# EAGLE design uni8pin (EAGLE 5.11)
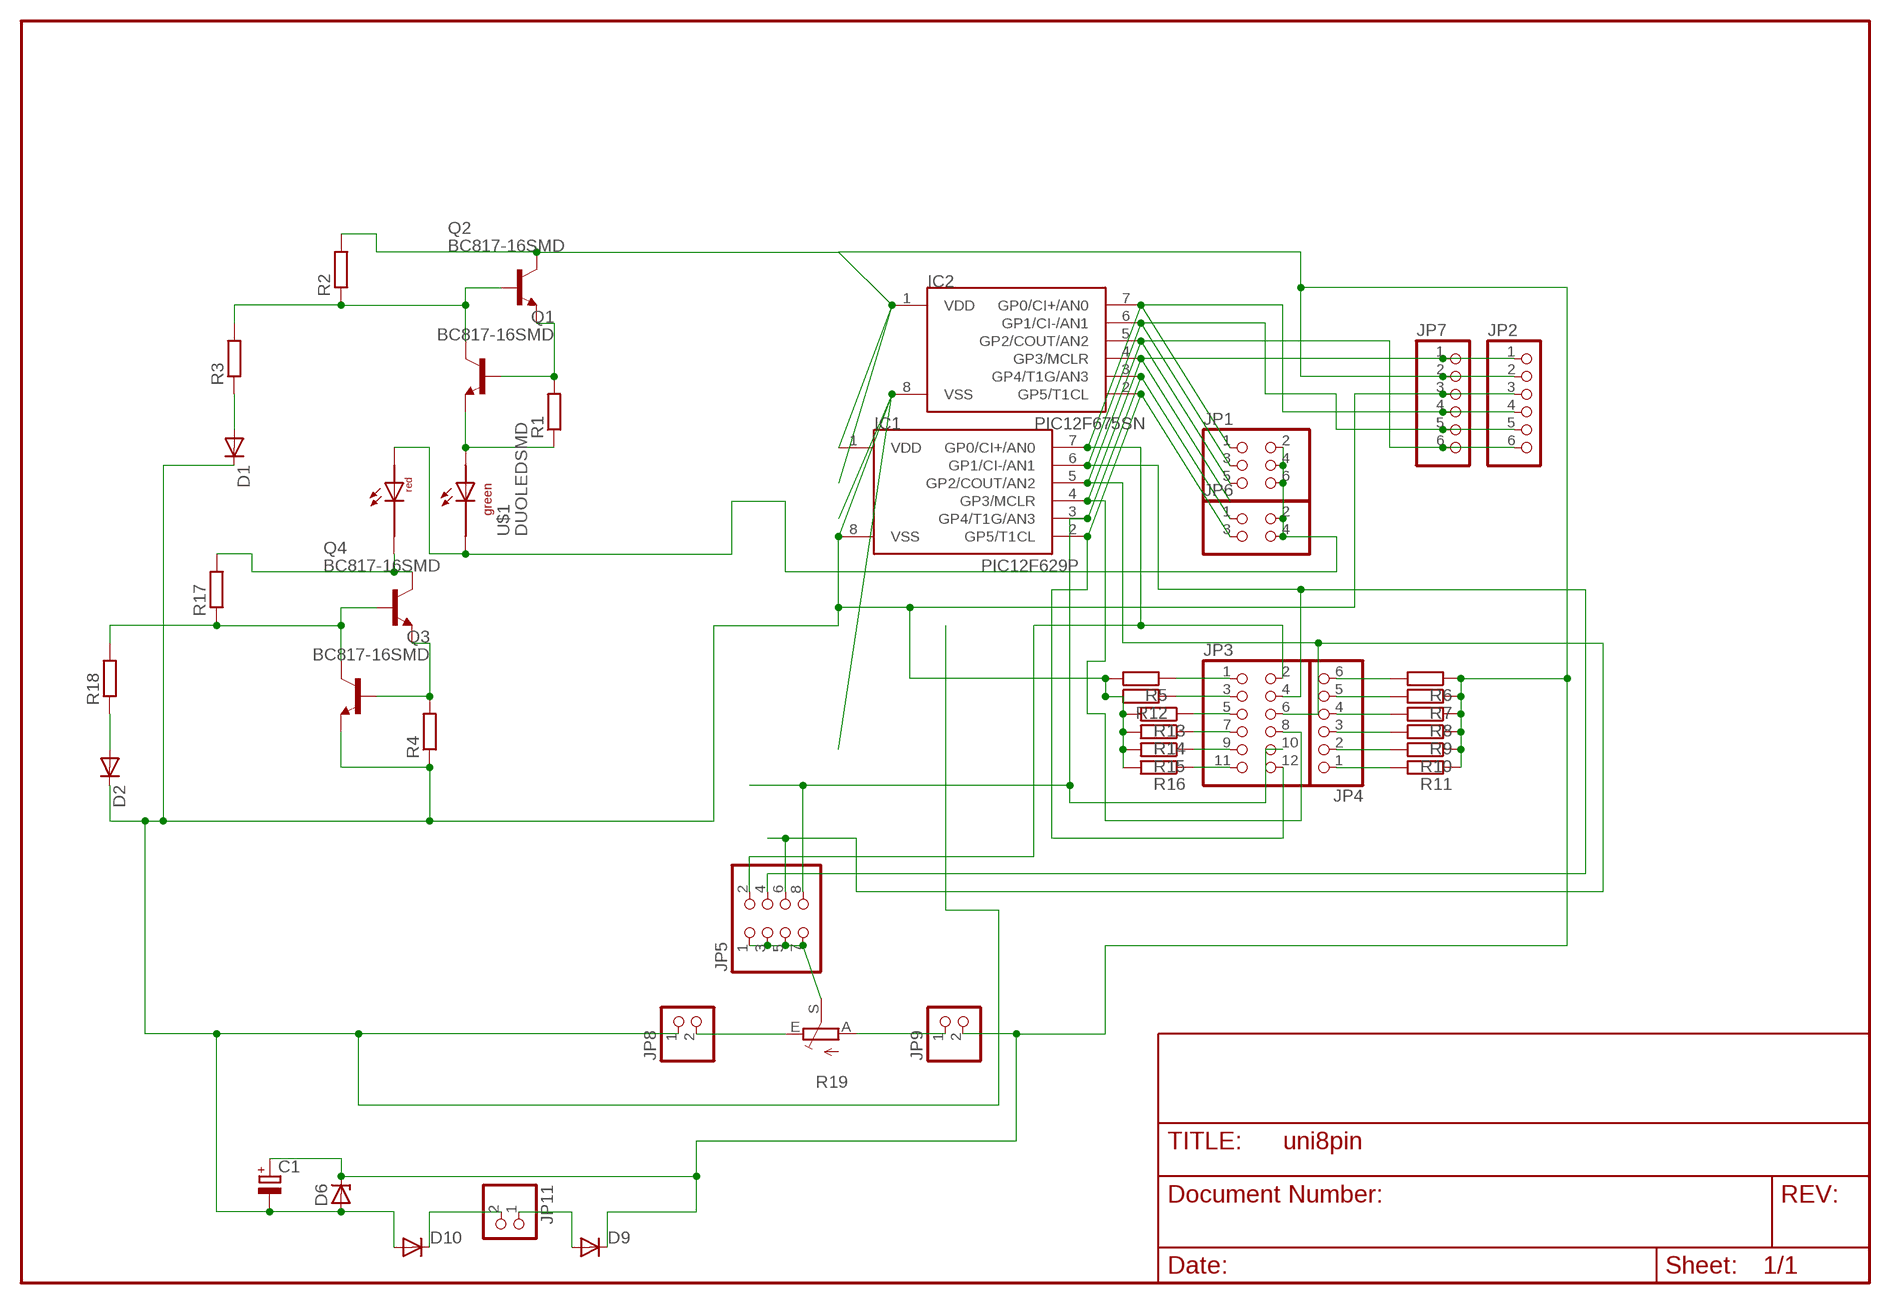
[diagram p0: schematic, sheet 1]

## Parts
C1  CPOL-EU5-13  [2,5-5-FLAT]
D1  DIODE-MINIMELF  [MINIMELF]
D2  DIODE-MINIMELF  [MINIMELF]
D6  ZENER-DIODEZD-2.5  [ZDIO-2.5]
D9  DIODE-D-5  [D-5]
D10  DIODE-D-5  [D-5]
IC1  PIC12F629P  [DIL8]
IC2  PIC12F675SN  [SO-08]
JP1  PINHD-2X3  [2X03]
JP2  PINHD-1X6  [1X06]
JP3  PINHD-2X6  [2X06]
JP4  PINHD-1X6  [1X06]
JP5  PINHD-2X4  [2X04]
JP6  PINHD-2X2  [2X02]
JP7  PINHD-1X6  [1X06]
JP8  PINHD-1X2  [1X02]
JP9  PINHD-1X2  [1X02]
JP11  PINHD-1X2  [1X02]
Q1  BC817-16SMD  [SOT23-BEC]
Q2  BC817-16SMD  [SOT23-BEC]
Q3  BC817-16SMD  [SOT23-BEC]
Q4  BC817-16SMD  [SOT23-BEC]
R1  R-EU_R1206  [R1206]
R2  R-EU_R1206  [R1206]
R3  R-EU_R1206  [R1206]
R4  R-EU_R1206  [R1206]
R5  R-EU_R1206  [R1206]
R6  R-EU_R1206  [R1206]
R7  R-EU_R1206  [R1206]
R8  R-EU_R1206  [R1206]
R9  R-EU_R1206  [R1206]
R10  R-EU_R1206  [R1206]
R11  R-EU_R1206  [R1206]
R12  R-EU_R1206  [R1206]
R13  R-EU_R1206  [R1206]
R14  R-EU_R1206  [R1206]
R15  R-EU_R1206  [R1206]
R16  R-EU_R1206  [R1206]
R17  R-EU_R1206  [R1206]
R18  R-EU_R1206  [R1206]
R19  TRIM_EU-RAND160  [RANDL]
U$1  DUOLEDSMD  [DUOLEDSMD]

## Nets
N$1: IC1.3(GP4/T1G/AN3) IC2.3(GP4/T1G/AN3) JP3.10 JP5.8 JP6.1
N$2: Q2.C R2.2
N$3: Q1.E R1.1 U$1.AGRN
N$4: JP1.2 JP1.4 JP1.6 JP6.2 JP6.4 U$1.ARED U$1.CGRN
N$5: C1.- D1.C D2.C D6.A D10.A IC1.8(VSS) IC2.8(VSS) JP2.3 JP7.3 JP8.1 Q3.E R4.1 R5.2 R12.2 R13.2 R14.2 R15.2 R16.2
N$6: C1.+ D6.C D9.C IC1.1(VDD) IC2.1(VDD) JP2.2 JP7.2 JP9.2 R6.1 R7.1 R8.1 R9.1 R10.1 R11.1
N$7: Q1.B Q2.E R1.2
N$8: Q1.C Q2.B R2.1 R3.2
N$9: IC1.2(GP5/T1CL) IC2.2(GP5/T1CL) JP3.12 JP6.3
N$10: D1.A R3.1
N$11: IC1.4(GP3/MCLR) IC2.4(GP3/MCLR) JP2.1 JP3.8 JP7.1
N$12: IC1.5(GP2/COUT/AN2) IC2.5(GP2/COUT/AN2) JP1.5 JP2.6 JP3.6 JP5.6 JP7.6
N$13: IC1.6(GP1/CI-/AN1) IC2.6(GP1/CI-/AN1) JP1.3 JP2.5 JP3.4 JP5.4 JP7.5
N$14: IC1.7(GP0/CI+/AN0) IC2.7(GP0/CI+/AN0) JP1.1 JP2.4 JP3.2 JP5.2 JP7.4
N$15: JP4.6 R6.2
N$16: JP4.5 R7.2
N$17: JP4.4 R8.2
N$18: JP4.3 R9.2
N$19: JP4.2 R10.2
N$20: JP4.1 R11.2
N$21: JP3.1 R5.1
N$22: JP3.3 R12.1
N$23: JP3.5 R13.1
N$24: JP3.7 R14.1
N$25: JP3.9 R15.1
N$26: JP3.11 R16.1
N$27: Q4.C R17.2 U$1.CRED
N$28: JP5.1 JP5.3 JP5.5 JP5.7 R19.S
N$29: Q3.B Q4.E R4.2
N$30: Q3.C Q4.B R17.1 R18.2
N$31: JP9.1 R19.A
N$32: JP8.2 R19.E
N$34: D10.C JP11.2
N$35: D9.A JP11.1
N$36: D2.A R18.1

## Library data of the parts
C1 = rcl-2:CPOL-EU: POLARIZED CAPACITOR, European symbol
D1 D2 = diode:DIODE-: DIODE
D6 = diode-1:ZENER-DIODE: Z-Diode
D9 D10 = diode-1:DIODE-: DIODE
IC1 IC2 = microchip-5:PIC12F6*: uPC nW 1k Program Flash memory 2x Timer Comparator 10b A/D converter/ 4xIN
JP1 = pinhead(2):PINHD-2X3: PIN HEADER
JP2 JP7 = pinhead:PINHD-1X6: PIN HEADER
JP3 = pinhead(2):PINHD-2X6: PIN HEADER
JP4 = pinhead(2):PINHD-1X6: PIN HEADER
JP5 = pinhead(2):PINHD-2X4: PIN HEADER
JP6 = pinhead(2):PINHD-2X2: PIN HEADER
JP8 JP9 JP11 = pinhead(2):PINHD-1X2: PIN HEADER
Q1-Q4 = transistor-npn:BC817*: NPN Transistor
R1-R4 R17 R18 = rcl:R-EU_: RESISTOR, European symbol
R5-R16 = rcl-2:R-EU_: RESISTOR, European symbol
R19 = pot:TRIM_EU-: POTENTIOMETER
U$1 = led:DUOLEDSMD

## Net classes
0 default: width 0.3 mm, drill 0.6 mm, clearance 0.2 mm
1 power: width 0.4 mm, drill 0.6 mm, clearance 0.2 mm

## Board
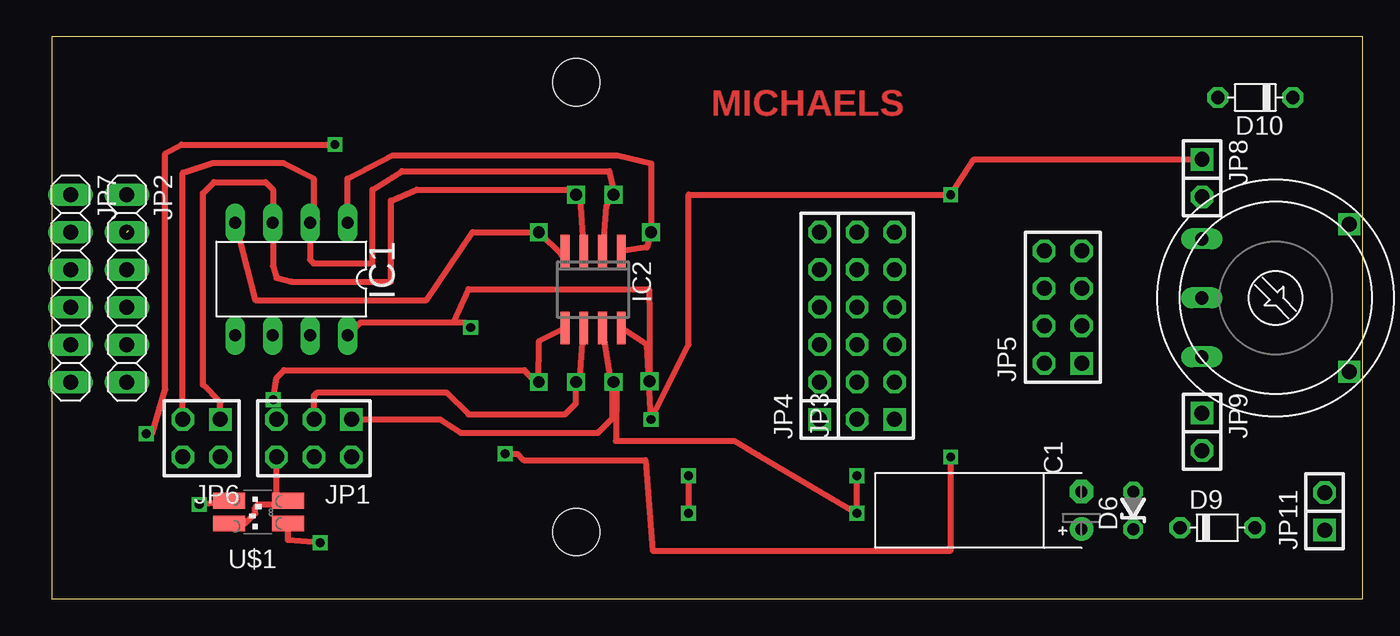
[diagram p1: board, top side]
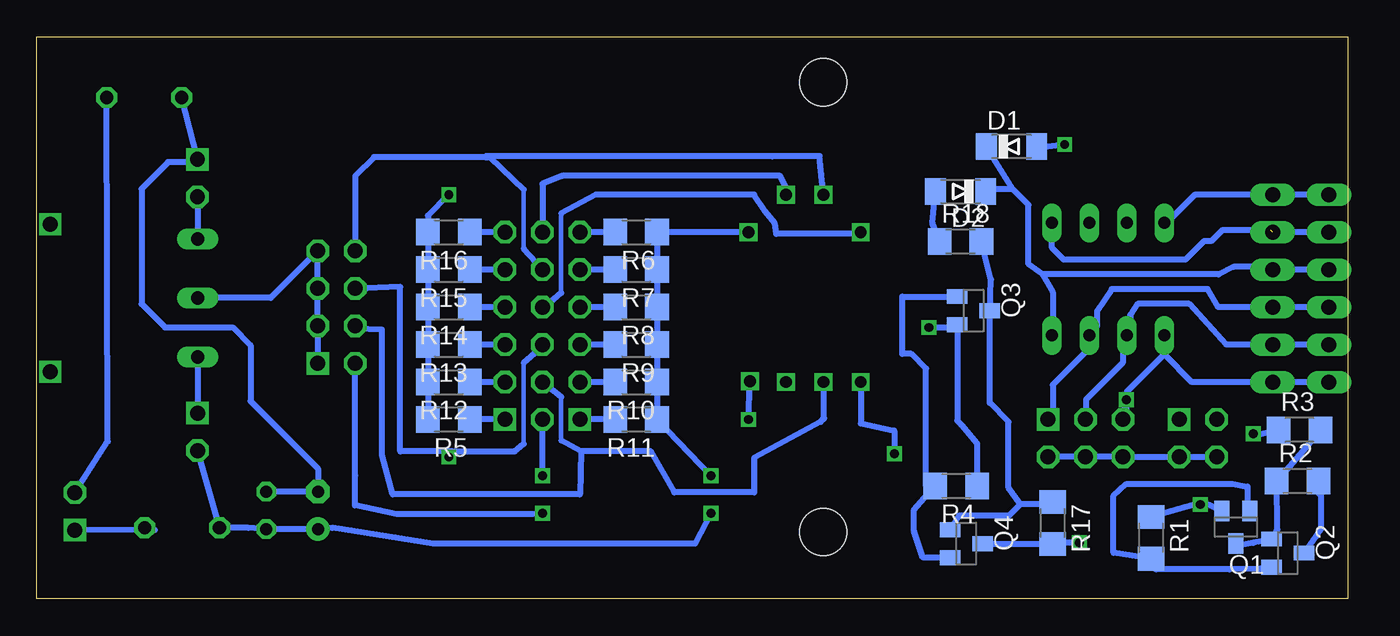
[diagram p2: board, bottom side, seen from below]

Size 88.9 x 38.1 mm. Coordinates in mm from the lower left corner, seen from the top.
Outline: 0,0 88.9,0 88.9,38.1 0,38.1 0,0
Copper layers (1*16): Top 0.035mm / dielectric 1.5mm / Bottom 0.035mm
Design rules "default": minimum track width 10mil, minimum drill 24mil, track to track 8mil, track to pad 8mil, pad to pad 8mil, via to via 8mil, smd to smd 8mil, copper to edge 40mil, drill to drill 8mil, minimum pad ring 10mil, minimum via ring 8mil, stop-mask expansion 4mil, vias tented up to drill 0mil, thermal gap 10mil
Holes 3.2 mm at 35.56,35.02 35.56,4.54

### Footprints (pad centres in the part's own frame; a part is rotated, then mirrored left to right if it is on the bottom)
2,5-5-FLAT = drill 0.813 pad 1.6 round: + -1.27,0 | drill 0.813 pad 1.6 octagon: - 1.27,0
MINIMELF = smd 1.4 x 1.8: A 1.7,0; C -1.7,0
ZDIO-2.5 = drill 0.813 octagon: A 1.27,0; C -1.27,0
D-5 = drill 0.9 octagon: A 2.54,0; C -2.54,0
DIL8 = drill 0.813 long: 1 -3.81,-3.81; 2 -1.27,-3.81; 3 1.27,-3.81; 4 3.81,-3.81; 5 3.81,3.81; 6 1.27,3.81; 7 -1.27,3.81; 8 -3.81,3.81
SO-08 = smd 0.6 x 2.2: 1 -1.905,-2.6; 2 -0.635,-2.6; 3 0.635,-2.6; 4 1.905,-2.6; 5 1.905,2.6; 6 0.635,2.6; 7 -0.635,2.6; 8 -1.905,2.6
2X03 = drill 1.016 square: 1 -2.54,-1.27 | drill 1.016 octagon: 2 -2.54,1.27; 3 0,-1.27; 4 0,1.27; 5 2.54,-1.27; 6 2.54,1.27
1X06 = drill 1.016 long: 1 -6.35,0; 2 -3.81,0; 3 -1.27,0; 4 1.27,0; 5 3.81,0; 6 6.35,0
2X06 = drill 1.016 square: 1 -6.35,-1.27 | drill 1.016 octagon: 2 -6.35,1.27; 3 -3.81,-1.27; 4 -3.81,1.27; 5 -1.27,-1.27; 6 -1.27,1.27; 7 1.27,-1.27; 8 1.27,1.27; 9 3.81,-1.27; 10 3.81,1.27; 11 6.35,-1.27; 12 6.35,1.27
1X06' = drill 1.016 square: 1 -6.35,0 | drill 1.016 octagon: 2 -3.81,0; 3 -1.27,0; 4 1.27,0; 5 3.81,0; 6 6.35,0
2X04 = drill 1.016 square: 1 -3.81,-1.27 | drill 1.016 octagon: 2 -3.81,1.27; 3 -1.27,-1.27; 4 -1.27,1.27; 5 1.27,-1.27; 6 1.27,1.27; 7 3.81,-1.27; 8 3.81,1.27
2X02 = drill 1.016 square: 1 -1.27,-1.27 | drill 1.016 octagon: 2 -1.27,1.27; 3 1.27,-1.27; 4 1.27,1.27
1X02 = drill 1.016 square: 1 -1.27,0 | drill 1.016 octagon: 2 1.27,0
SOT23-BEC = smd 1 x 1.4: B -0.95,-1.1; C 0,1.1; E 0.95,-1.1
R1206 = smd 1.6 x 1.803: 1 -1.422,0; 2 1.422,0
RANDL = drill 0.9 long: A -4,5; E 4,5; S 0,5 | drill 1 square: P$1 -5,-5; P$2 5,-5
DUOLEDSMD = smd 1.067 x 2.184: AGRN 0.77,1.95; ARED -0.77,1.95; CGRN 0.77,-2.05; CRED -0.77,-2.05

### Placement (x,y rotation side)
C1  69.83,6 90 top
D1  22.8,30.66 0 bottom
D2  26.26,27.62 180 bottom
D6  73.34,6 90 top
D9  79.05,4.82 0 top
D10  81.62,33.99 180 top
IC1  16.24,21.68 180 top
IC2  36.71,20.97 180 top
JP1  17.78,10.89 180 top
JP2  5.08,21.05 270 top
JP3  55.88,18.51 90 top
JP4  [1X06']  52.07,18.51 90 top
JP5  68.58,19.78 90 top
JP6  10.16,10.89 180 top
JP7  1.27,21.05 270 top
JP8  78.01,28.52 270 top
JP9  78,11.32 270 top
JP11  86.32,5.93 90 top
Q1  7.58,4.86 180 bottom
Q2  4.06,3.1 270 bottom
Q3  25.38,19.54 270 bottom
Q4  25.86,3.74 270 bottom
R1  13.32,4.14 270 bottom
R2  3.4,7.98 0 bottom
R3  3.26,11.46 0 bottom
R4  26.56,7.66 180 bottom
R5  60.96,12.16 180 bottom
R6  48.26,24.86 180 bottom
R7  48.26,22.32 180 bottom
R8  48.26,19.78 180 bottom
R9  48.26,17.24 180 bottom
R10  48.26,14.7 180 bottom
R11  48.26,12.16 180 bottom
R12  60.96,14.7 180 bottom
R13  60.96,17.24 180 bottom
R14  60.96,19.78 180 bottom
R15  60.96,22.32 180 bottom
R16  60.96,24.86 180 bottom
R17  20,5.14 270 bottom
R18  26.26,24.22 0 bottom
R19  83,20.4 90 top
U$1  13.97,5.88 90 top

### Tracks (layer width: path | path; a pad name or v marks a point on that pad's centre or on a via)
N$1  (via drill 0.8)
  Top 0.406: JP6.1 11.43,13.32 10.25,14.5 10.25,27.5 11,28.25 14.5,28.25 15,27.75 15,25.25 | 15,25.25 14.97,25.28 IC1.3 | IC2.3 35.83,27.14 v35.56,27.4 35.6,27.4 | 15,25.25 15,22.56 15.24,21.76 16.25,21.5 23,21.5 23,27 24.75,27.75 35.25,27.75 35.6,27.4 | 35.6,27.4 35.75,27.25
  Bottom 0.305: 55.88,27.75 55.88,23.75
  Bottom 0.406: JP5.8 67.31,28.67 66.04,29.94 58.5,29.94 | 58.5,29.94 58.19,29.94 55.88,27.75 | JP3.10 54.61,22.36 55.88,23.75 | v35.56,27.4 35.81,30.01 39.04,30 58.5,30 58.5,29.94
N$2
  Bottom 0.406: Q2.C 2.16,4.24 1.8,4.8 1.8,7 1.98,7.18 R2.2
N$3  (via drill 0.6)
  Top 0.406: v10,6.4 11.97,6.6 U$1.AGRN
  Bottom 0.406: Q1.E 9.76,6.56 v10,6.4 9.84,6.56 R1.1
N$4
  Top 0.406: 15.4,6.65 U$1.CGRN | 15.4,6.65 15.24,6.65 JP1.6 | U$1.ARED 13.11,5.11 13.8,5.8 13.8,6.2 14,6.4 15.15,6.4 15.4,6.65
  Bottom 0.406: JP1.2 JP1.4 JP1.6 JP6.2 JP6.4
N$5  (via drill 0.6, 0.8)
  Top 0.406: IC2.8 40.37,17.23 v40.64,12.16 43.18,17.24 43.18,27.4 v60.96,27.4 62.55,29.79 JP8.1 | v40.54,14.75 40.54,19.21 40.5,21 28.25,21 27.25,18.75 | 27.25,18.75 20.93,18.75 IC1.8 | 27.25,18.75 28.05,18.75 v28.4,18.4
  Bottom 0.406: v40.54,14.75 40.59,14.7 v40.64,12.16 | v60.96,27.4 62.38,25.98 R16.2 R15.2 R14.2 R13.2 R12.2 R5.2 | D6.A C1.- 69.83,8.83 74.4,13.4 74.4,17.2 75.6,18.4 80.2,18.4 81.8,20 81.8,27.8 80,29.6 78.2,29.6 JP8.1 D10.A | JP7.3 JP2.3 5.26,22.5 7.75,22.5 8.75,22 20.7,22 | R4.1 25.13,10.53 26.2,11.8 26.48,12.08 Q3.E 26.67,18.4 v28.4,18.4 | 22.7,27.76 D1.C | 20.7,22 21.65,22.7 21.65,26.71 22.7,27.76 | 20.7,22 20,20.8 20,17.92 IC1.8 | 22.7,27.76 24.42,27.76 D2.C
N$6  (via drill 0.6, 0.8)  (1 unrouted)
  Top 0.406: IC2.1 40.37,23.84 v40.64,24.86 40.64,29.52 38.35,30.06 23.11,30.06 20.05,28.5 IC1.1 | v43.18,8.35 v43.18,5.81
  Bottom 0.406: 46.93,22.32 46.84,22.41 R6.1 v40.64,24.86 | 46.8,14.7 46.75,14.75 | 46.8,14.7 R10.1 46.84,17.09 46.99,17.24 | 46.8,14.7 46.84,14.66 R11.1 v43.18,8.35 | 46.99,17.24 47,17.25 | 46.99,17.24 R9.1 R8.1 | R8.1 46.84,19.91 46.75,20 | 46.93,22.32 47,22.25 46.84,22.09 R8.1 | 46.93,22.32 R7.1 | IC1.1 20.05,23.8 19.25,23 11,23 9.75,24.25 9.25,24.25 8.5,25 5.22,25 | v43.18,5.81 44.26,3.75 62.04,3.75 68.85,4.81 C1.+ D6.C 74.54,4.82 D9.C JP9.2 | JP7.2 JP2.2
N$7
  Bottom 0.406: Q1.B 6.8,6.59 6.8,7.6 7.8,7.8 15,7.8 15.88,7 15.88,3.12 R1.2 13,2 8,2 5.96,2.04 Q2.E
N$8
  Bottom 0.406: Q1.C 7.64,3.76 7.4,3.6 6.41,3.8 Q2.B 4.76,4.72 R2.1 2.82,10.28 R3.2
N$9  (via drill 0.8)
  Top 0.406: IC2.2 37.59,26.64 v38.1,27.4 38.1,27.44 38.04,27.5 38.04,27.96 37.79,29 23.75,29 21.75,27.75 21.75,22.75 17.75,22.75 17.51,22.99 IC1.2 17.51,25.26 | JP6.3 8.89,28.89 10.95,29.55 15.7,29.55 17.75,28.5 17.75,26 18,25.75 17.51,25.26 | 17.51,25.26 17.5,25.25
  Bottom 0.406: JP3.12 54.61,28.14 53.25,28.67 38.5,28.67 38.1,27.84 v38.1,27.4
N$10  (via drill 0.6)
  Top 0.406: v6.4,11.2 6.8,11.2 7.7,14.2 7.7,30.2 8.8,30.8 v19.2,30.8
  Bottom 0.406: R3.1 6.26,11.06 v6.4,11.2 | D1.A 20.34,30.66 v19.2,30.8
N$11  (via drill 0.8)
  Top 0.406: IC2.4 34.55,23.32 v33.02,24.86 28.55,24.86 25.4,20.25 13.8,20.25 IC1.4
  Bottom 0.305: 53.34,26.13 53.34,20.75
  Bottom 0.406: 12.43,25.32 12.5,25.25 | 12.43,25.32 IC1.4 | 12.43,25.32 10.35,27.4 JP2.1 JP7.1 | JP3.8 54.47,19.78 53.34,20.75 | 53.34,26.13 51,27.4 40.25,27.4 39.5,26.25 38.85,25.45 38.75,24.75 32.75,24.75 32.86,24.86 v33.02,24.86
N$12  (via drill 0.6, 0.8)
  Top 0.406: IC2.5 33.05,17.48 v33.02,14.7 33.02,14.52 | v15,13.5 15.25,15 15.75,15.5 32.04,15.5 33.02,14.52 | 33.02,14.52 33.04,14.5 | v60.96,9.62 60.96,3.27 40.75,3.27 40.25,9.4 32,9.4 31.57,9.83 v30.75,9.83
  Bottom 0.305: 55.88,10.5 55.88,16
  Bottom 0.406: v33.02,14.7 33.02,11.9 30.75,11.4 v30.75,9.83 | 12.43,16.57 IC1.5 | 12.43,16.57 15,14 15,12.25 15.24,12.01 | 15.24,12.01 v15,13.5 | 15.24,12.01 JP1.5 | JP5.6 66.55,21.05 64.25,21.15 64.25,10 60.71,10 | 60.71,10 56.5,10 55.88,10.5 | JP3.6 54.61,17.14 55.88,16 | v60.96,9.62 60.71,10 | JP7.6 JP2.6 10.55,14.7 12.43,16.57
N$13  (via drill 0.8)
  Top 0.406: IC2.6 35.83,14.96 v35.56,14.7 35.59,14.7 35.79,14.5 35.54,14.25 35.54,13.25 34.79,12.5 28.25,12.5 26.75,14 18,14 17.78,13.78 JP1.3
  Bottom 0.305: 53.34,10.75 53.34,13.7
  Bottom 0.406: 15.13,17.87 15.25,17.75 15.25,16 17.75,13.5 17.75,12 17.78,12.03 JP1.3 | 15.13,17.87 IC1.6 | 15.13,17.87 14.75,18.25 14.75,19.25 14.25,20 10.75,20 8.24,17.24 JP2.5 JP7.5 | v35.56,14.7 35.56,12.25 | 35.56,12.25 35.56,12.16 | 54.61,14.36 JP3.4 53.34,13.7 | JP5.4 67.31,18.31 65.5,18.25 65.5,9.75 64.77,7.08 52.07,7.08 52,10 | 52,10 53.34,10.75 | 52,10 47.25,10 45.67,7.21 40.25,7.21 40.25,9.55 35.75,12 35.5,12.25 35.56,12.25
N$14  (via drill 0.6, 0.8)
  Top 0.406: IC2.7 37.84,15.21 v38.1,14.7 v38.1,14.69 38.29,14.5 | JP1.1 26.34,12.16 27.75,11.25 37.04,11.25 38.04,12.25 38.04,14.25 38.29,14.5 | 38.29,14.5 38.25,10.71 46.29,10.71 47.92,9.75 v54.61,5.81 v54.61,8.35
  Bottom 0.406: JP1.1 20.32,12.18 20,12.5 20,14.5 17.51,16.99 IC1.7 17.51,17.99 17,18.5 17,19.5 16,21 9.5,21 8.78,19.78 JP2.4 JP7.4 | JP5.2 67.31,8.35 67.33,8.33 67.33,6.33 64.5,5.75 55.25,5.75 v54.61,5.81 | v54.61,8.35 JP3.2
N$15
  Bottom 0.406: R6.2 JP4.6
N$16
  Bottom 0.406: R7.2 JP4.5
N$17
  Bottom 0.406: R8.2 JP4.4
N$18
  Bottom 0.406: R9.2 JP4.3
N$19
  Bottom 0.406: R10.2 JP4.2
N$20
  Bottom 0.406: R11.2 JP4.1
N$21
  Bottom 0.406: JP3.1 R5.1
N$22
  Bottom 0.406: JP3.3 R12.1
N$23
  Bottom 0.406: JP3.5 R13.1
N$24
  Bottom 0.406: JP3.7 R14.1
N$25
  Bottom 0.406: JP3.9 R15.1
N$26
  Bottom 0.406: JP3.11 R16.1
N$27  (via drill 0.6)
  Top 0.406: U$1.CRED 16.02,3.98 v18.2,3.8
  Bottom 0.406: v18.2,3.8 19.4,3.8 19.6,3.6 19.88,3.6 R17.2 24.74,3.72 Q4.C
N$28
  Bottom 0.406: R19.S 73.04,20.4 JP5.7 JP5.5 JP5.3 JP5.1
N$29
  Bottom 0.406: Q4.E 28.79,2.79 29.4,4.6 29.4,6.04 R4.2 28.6,7.64 28.6,15.6 29.6,16.6 30.2,16.6 30.2,20.49 Q3.B
N$30
  Bottom 0.406: 22.2,6.4 23,7.54 23,12 24.28,13.28 Q3.C 24.18,21.64 R18.2 | 22.2,6.4 20.16,6.4 R17.1 | Q4.B 26.36,5.64 22.96,5.64 22.2,6.4
N$31
  Bottom 0.406: R19.A JP9.1
N$32
  Bottom 0.406: JP8.2 R19.E
N$34
  Bottom 0.406: JP11.2 84.08,10.68 D10.C
N$35
  Bottom 0.406: D9.A 80.88,4.68 JP11.1
N$36
  Bottom 0.406: D2.A 28.16,25.5 R18.1

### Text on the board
Top: MICHAELS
